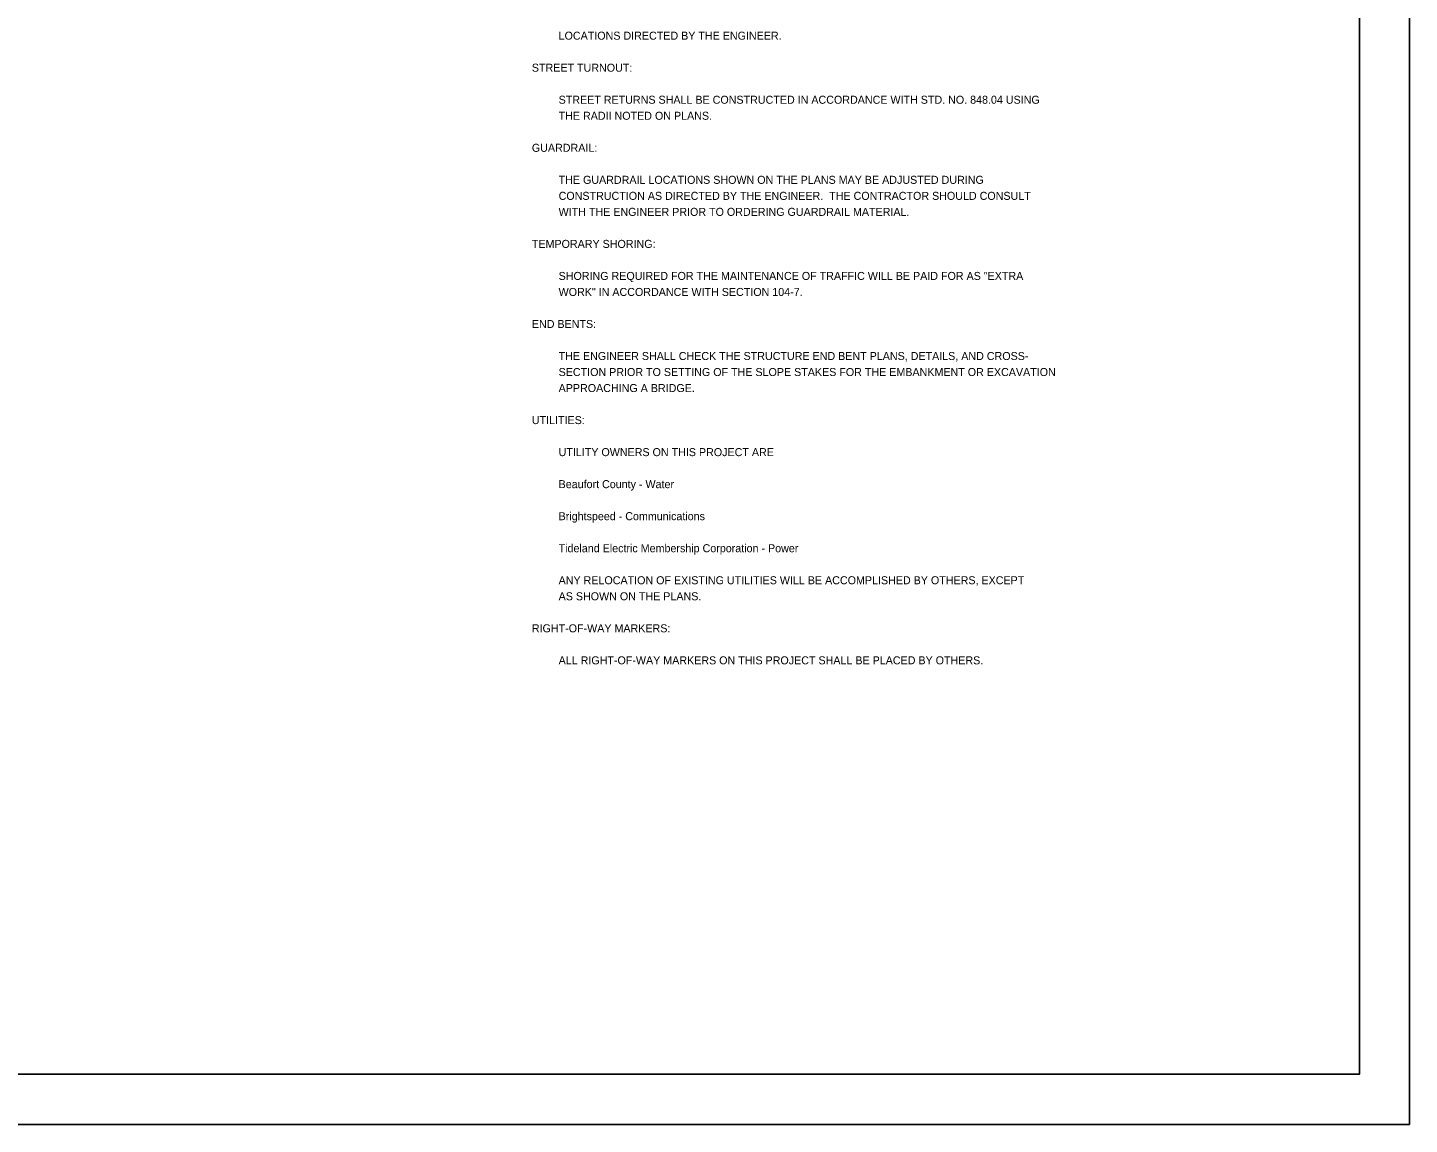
# Model space of a CAD drawing. Extents: x 885343.6 to 885383.5, y 651350.8 to 651372.8.
# Drawn here: x 885363.79 to 885377.6, y 651350.76 to 651361.72 of the extents above; entities that cross this region are included whole.
import ezdxf

# ---------------------------------------------------------------- set-up
doc = ezdxf.new("R2010")
doc.units = 0
for name, color, linetype in [('Sheet Data Text CELL', 7, 'Continuous'), ('Sheet Plan CELL', 7, 'Continuous'), ('Stewart Plot Border Xerox6279 and LJ5000', 7, 'Continuous')]:
    doc.layers.add(name, color=color, linetype=linetype)

msp = doc.modelspace()

# ---------------------------------------------------------------- linework, layer by layer
at = {"layer": 'Sheet Plan CELL'}
msp.add_lwpolyline([(885377.098, 651372.262), (885347.098, 651372.262), (885347.098, 651351.262), (885377.098, 651351.262)], close=True, dxfattribs=at)
at = {"layer": 'Stewart Plot Border Xerox6279 and LJ5000'}
msp.add_lwpolyline([(885343.598, 651372.762), (885377.598, 651372.762), (885377.598, 651350.762), (885343.598, 651350.762)], close=True, dxfattribs=at)

# ---------------------------------------------------------------- texts
at = {"layer": 'Sheet Data Text CELL'}
for s, p in [('         LOCATIONS DIRECTED BY THE ENGINEER.  ', (885368.827, 651361.597)), ('STREET TURNOUT:  ', (885368.827, 651361.277)), ('         STREET RETURNS SHALL BE CONSTRUCTED IN ACCORDANCE WITH STD. NO. 848.04 USING ', (885368.827, 651360.957)), ('         THE RADII NOTED ON PLANS.  ', (885368.827, 651360.797)), ('GUARDRAIL:  ', (885368.827, 651360.477)), ('         THE GUARDRAIL LOCATIONS SHOWN ON THE PLANS MAY BE ADJUSTED DURING ', (885368.827, 651360.157)), ('         CONSTRUCTION AS DIRECTED BY THE ENGINEER.  THE CONTRACTOR SHOULD CONSULT', (885368.827, 651359.997)), ('         WITH THE ENGINEER PRIOR TO ORDERING GUARDRAIL MATERIAL.', (885368.827, 651359.837)), ('TEMPORARY SHORING:  ', (885368.827, 651359.517)), ('         SHORING REQUIRED FOR THE MAINTENANCE OF TRAFFIC WILL BE PAID FOR AS "EXTRA ', (885368.827, 651359.197)), ('         WORK" IN ACCORDANCE WITH SECTION 104-7.  ', (885368.827, 651359.037)), ('END BENTS:  ', (885368.827, 651358.717)), ('         THE ENGINEER SHALL CHECK THE STRUCTURE END BENT PLANS, DETAILS, AND CROSS-', (885368.827, 651358.397)), ('         SECTION PRIOR TO SETTING OF THE SLOPE STAKES FOR THE EMBANKMENT OR EXCAVATION ', (885368.827, 651358.237)), ('         APPROACHING A BRIDGE.  ', (885368.827, 651358.077)), ('UTILITIES:  ', (885368.827, 651357.757)), ('         UTILITY OWNERS ON THIS PROJECT ARE  ', (885368.827, 651357.437)), ('         Beaufort County - Water', (885368.827, 651357.117)), ('         Brightspeed - Communications', (885368.827, 651356.797)), ('         Tideland Electric Membership Corporation - Power', (885368.827, 651356.477)), ('         ANY RELOCATION OF EXISTING UTILITIES WILL BE ACCOMPLISHED BY OTHERS, EXCEPT ', (885368.827, 651356.157)), ('         AS SHOWN ON THE PLANS.  ', (885368.827, 651355.997)), ('RIGHT-OF-WAY MARKERS:  ', (885368.827, 651355.677)), ('         ALL RIGHT-OF-WAY MARKERS ON THIS PROJECT SHALL BE PLACED BY OTHERS.  ', (885368.827, 651355.357))]:
    msp.add_text(s, height=0.08, dxfattribs=at).set_placement(p)

doc.saveas('drawing.dxf')
